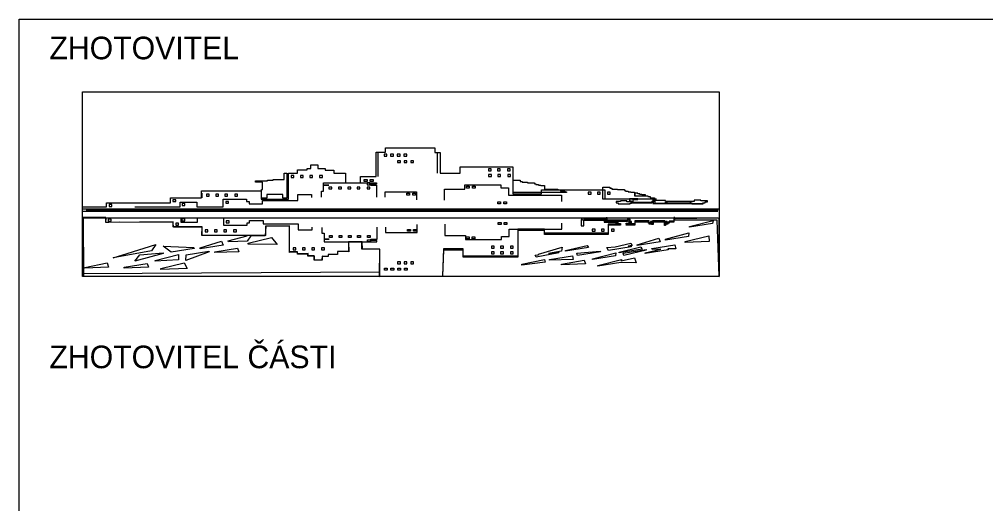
# Model space of a CAD drawing. Extents: x -740053 to -737517, y -1033516 to -1032476.
# Drawn here: x -739091.38 to -739059.3, y -1032591.95 to -1032575.88 of the extents above; entities that cross this region are included whole.
import ezdxf

# ---------------------------------------------------------------- set-up
doc = ezdxf.new("R2010")
doc.units = 0
doc.layers.add('promika-rozp', color=7, linetype='Continuous')

# ---------------------------------------------------------------- blocks, each defined once
blk = doc.blocks.new('onegast')
for p, q in [((22.998, 7.759), (22.998, 9.646)), ((27.598, 8.019), (27.598, 9.571)), ((6.825, 5.723), (6.825, 6.082)), ((9.252, 6.105), (9.252, 6.463)), ((9.309, 6.102), (9.309, 6.46)), ((0.046, 5.264), (49.513, 5.263)), ((0.046, 5.075), (49.427, 5.075)), ((0.046, 4.561), (49.435, 4.561)), ((0.278, 5.186), (49.435, 5.186))]:
    blk.add_line(p, q)
for points in [[(0, 14.352), (49.53, 14.352), (49.53, 0), (0, 0)], [(23.451, 9.351), (23.667, 9.351), (23.667, 9.502), (23.451, 9.502)], [(23.957, 9.351), (24.173, 9.351), (24.173, 9.502), (23.957, 9.502)], [(24.48, 9.351), (24.696, 9.351), (24.696, 9.502), (24.48, 9.502)], [(24.994, 9.351), (25.21, 9.351), (25.21, 9.502), (24.994, 9.502)], [(24.501, 8.843), (24.717, 8.843), (24.717, 8.994), (24.501, 8.994)], [(25.007, 8.843), (25.223, 8.843), (25.223, 8.994), (25.007, 8.994)], [(25.53, 8.843), (25.746, 8.843), (25.746, 8.994), (25.53, 8.994)], [(21.914, 7.53), (22.13, 7.53), (22.13, 7.378), (21.914, 7.378)], [(22.377, 7.53), (22.593, 7.53), (22.593, 7.378), (22.377, 7.378)], [(19.161, 6.799), (19.377, 6.799), (19.377, 6.95), (19.161, 6.95)], [(29.857, 7.022), (30.073, 7.022), (30.073, 6.871), (29.857, 6.871)], [(30.32, 7.022), (30.536, 7.022), (30.536, 6.871), (30.32, 6.871)], [(25.216, 6.462), (25.432, 6.462), (25.432, 6.311), (25.216, 6.311)], [(25.679, 6.462), (25.895, 6.462), (25.895, 6.311), (25.679, 6.311)], [(32.298, 5.793), (32.514, 5.793), (32.514, 5.642), (32.298, 5.642)], [(32.761, 5.793), (32.977, 5.793), (32.977, 5.642), (32.761, 5.642)], [(32.333, 4.18), (32.549, 4.18), (32.549, 4.029), (32.333, 4.029)], [(32.796, 4.18), (33.012, 4.18), (33.012, 4.029), (32.796, 4.029)], [(12.874, 2.574), (14.701, 3.028), (15.132, 2.483), (12.879, 2.512)], [(19.195, 3.182), (19.411, 3.182), (19.411, 3.031), (19.195, 3.031)], [(25.286, 3.656), (25.502, 3.656), (25.502, 3.505), (25.286, 3.505)], [(25.749, 3.656), (25.965, 3.656), (25.965, 3.505), (25.749, 3.505)], [(29.843, 3.074), (30.059, 3.074), (30.059, 2.923), (29.843, 2.923)], [(30.306, 3.074), (30.522, 3.074), (30.522, 2.923), (30.306, 2.923)], [(3.464, 1.792), (5.689, 2.483), (5.353, 1.985), (2.388, 1.451)], [(6.257, 2.359), (8.663, 2.239), (8.678, 2.175), (6.892, 1.886)], [(9.139, 2.21), (10.813, 2.729), (10.929, 2.436), (9.143, 2.148)], [(4.449, 1.687), (6.263, 1.842), (6.277, 1.778), (4.06, 1.174)], [(5.644, 1.239), (7.471, 1.693), (7.457, 1.283), (5.649, 1.176)], [(8.049, 1.674), (9.825, 1.965), (9.84, 1.9), (8.039, 1.247)], [(10.285, 1.911), (12.061, 2.202), (12.15, 1.899), (10.289, 1.849)], [(0.161, 0.692), (1.912, 1.059), (2.012, 0.718), (0.165, 0.63)], [(3.24, 0.71), (5.016, 1), (5.119, 0.715), (3.244, 0.648)], [(6.077, 0.602), (7.903, 1.057), (8.126, 0.622), (6.081, 0.54)], [(24.501, 0.974), (24.717, 0.974), (24.717, 1.125), (24.501, 1.125)], [(25.007, 0.974), (25.223, 0.974), (25.223, 1.125), (25.007, 1.125)], [(25.53, 0.974), (25.746, 0.974), (25.746, 1.125), (25.53, 1.125)], [(23.485, 0.631), (23.701, 0.631), (23.701, 0.48), (23.485, 0.48)], [(23.99, 0.631), (24.206, 0.631), (24.206, 0.48), (23.99, 0.48)], [(24.513, 0.631), (24.729, 0.631), (24.729, 0.48), (24.513, 0.48)], [(25.028, 0.631), (25.244, 0.631), (25.244, 0.48), (25.028, 0.48)]]:
    blk.add_lwpolyline(points, close=True)
for points in [[(0.046, 5.405), (1.862, 5.405), (1.862, 5.731), (6.84, 5.731), (6.84, 6.109), (9.238, 6.109), (9.238, 6.643), (13.878, 6.643), (13.878, 6.005), (16.015, 6.005), (16.015, 8.023), (16.706, 8.023), (16.706, 8.284), (17.475, 8.284), (17.475, 8.401), (17.749, 8.401), (17.749, 8.662), (18.296, 8.662), (18.296, 8.388), (18.879, 8.388), (18.879, 8.272), (19.556, 8.272), (19.556, 8.037), (20.443, 8.037), (20.443, 7.282), (21.616, 7.282), (21.616, 7.764), (22.841, 7.764), (22.841, 9.665), (23.57, 9.665), (23.57, 9.994), (27.389, 9.994), (27.389, 9.629), (27.806, 9.629), (27.806, 8.014), (29.37, 8.014), (29.37, 8.522), (33.462, 8.522), (33.462, 6.412), (35.707, 6.412), (35.707, 6.737), (40.62, 6.737), (40.62, 6.034), (44.351, 6.034), (44.351, 5.656), (48.313, 5.656)], [(31.563, 8.207), (31.779, 8.207), (31.779, 8.358), (31.563, 8.358), (31.563, 8.207)], [(32.276, 8.207), (32.493, 8.207), (32.493, 8.358), (32.276, 8.358), (32.276, 8.207)], [(33.049, 8.207), (33.265, 8.207), (33.265, 8.358), (33.049, 8.358), (33.049, 8.207)], [(14.328, 6.074), (13.905, 6.074), (13.905, 6.765), (14, 6.765), (14, 7.326), (13.453, 7.326), (13.453, 7.425), (14.378, 7.425), (14.378, 7.475), (14.825, 7.475), (14.825, 7.544), (15.233, 7.544), (15.273, 7.544), (15.68, 7.544), (15.68, 8.021), (15.879, 8.021), (15.879, 6.074), (15.571, 6.074), (15.571, 6.362), (14.328, 6.362), (14.328, 6.074)], [(16.228, 7.685), (16.444, 7.685), (16.444, 7.836), (16.228, 7.836), (16.228, 7.685)], [(16.952, 7.685), (17.168, 7.685), (17.168, 7.836), (16.952, 7.836), (16.952, 7.685)], [(17.666, 7.685), (17.882, 7.685), (17.882, 7.836), (17.666, 7.836), (17.666, 7.685)], [(18.439, 7.685), (18.655, 7.685), (18.655, 7.836), (18.439, 7.836), (18.439, 7.685)], [(31.581, 7.761), (31.797, 7.761), (31.797, 7.913), (31.581, 7.913), (31.581, 7.761)], [(32.295, 7.761), (32.511, 7.761), (32.511, 7.913), (32.295, 7.913), (32.295, 7.761)], [(33.067, 7.761), (33.284, 7.761), (33.284, 7.913), (33.067, 7.913), (33.067, 7.761)], [(18.576, 6.169), (18.576, 6.617), (18.746, 6.617), (18.746, 7.081), (19.149, 7.081), (19.149, 7.081), (18.746, 7.081), (18.746, 7.282), (22.862, 7.282), (22.862, 7.282), (22.862, 7.183), (22.396, 7.183), (22.396, 7.088), (22.871, 7.088), (22.871, 6.157)], [(19.919, 6.799), (20.135, 6.799), (20.135, 6.95), (19.919, 6.95), (19.919, 6.799)], [(20.644, 6.799), (20.86, 6.799), (20.86, 6.95), (20.644, 6.95), (20.644, 6.799)], [(21.358, 6.799), (21.574, 6.799), (21.574, 6.95), (21.358, 6.95), (21.358, 6.799)], [(22.13, 6.799), (22.346, 6.799), (22.346, 6.95), (22.13, 6.95), (22.13, 6.799)], [(22.141, 7.131), (22.357, 7.131), (22.357, 7.282), (22.141, 7.282), (22.141, 7.131)], [(28.148, 5.929), (28.148, 6.792), (28.724, 6.792), (28.724, 6.792), (29.741, 6.792), (29.741, 7.118), (30.144, 7.118), (30.144, 7.118), (30.97, 7.118), (30.97, 7.118), (32.543, 7.118), (32.543, 6.888), (33.138, 6.888), (33.138, 6.313), (37.246, 6.313), (37.246, 5.833)], [(37.637, 6.532), (33.482, 6.532), (33.482, 7.473), (34.037, 7.473), (34.037, 7.386), (34.193, 7.386), (34.193, 7.317), (34.616, 7.317), (34.616, 7.275), (35.159, 7.275), (35.159, 7.197), (35.257, 7.197), (35.257, 7.144), (35.467, 7.144), (35.467, 7.095), (35.652, 7.095), (35.652, 7.062), (35.94, 7.062), (35.94, 6.779), (36.976, 6.779), (36.976, 6.725), (37.165, 6.725), (37.165, 6.639), (37.502, 6.639), (37.502, 6.565), (37.637, 6.565), (37.637, 6.532)], [(40.466, 6.007), (40.466, 6.948), (41.021, 6.948), (41.021, 6.861), (41.177, 6.861), (41.177, 6.792), (41.6, 6.792), (41.6, 6.75), (42.143, 6.75), (42.143, 6.672), (42.241, 6.672), (42.241, 6.619), (42.451, 6.619), (42.451, 6.57), (42.636, 6.57), (42.636, 6.537), (42.924, 6.537), (42.924, 6.254), (43.96, 6.254), (43.96, 6.2), (44.149, 6.2), (44.149, 6.114), (44.486, 6.114), (44.486, 6.04), (44.622, 6.04), (44.622, 6.007), (40.466, 6.007)], [(44.622, 6.007), (40.466, 6.007), (40.466, 6.948), (41.021, 6.948), (41.021, 6.861), (41.177, 6.861), (41.177, 6.792), (41.6, 6.792), (41.6, 6.75), (42.143, 6.75), (42.143, 6.672), (42.241, 6.672), (42.241, 6.619), (42.451, 6.619), (42.451, 6.57), (42.636, 6.57), (42.636, 6.537), (42.924, 6.537), (42.924, 6.254), (43.96, 6.254), (43.96, 6.2), (44.149, 6.2), (44.149, 6.114), (44.486, 6.114), (44.486, 6.04), (44.622, 6.04), (44.622, 6.007)], [(4.051, 5.42), (7.596, 5.42), (7.596, 5.765), (8.897, 5.765), (8.897, 5.42), (10.933, 5.42), (10.933, 6.01), (12.761, 6.01), (12.761, 5.826), (12.957, 5.826), (12.957, 5.643), (14, 5.643), (14, 5.888), (16.736, 5.888), (16.736, 6.366), (17.815, 6.366), (17.815, 6.145)], [(9.628, 6.243), (9.844, 6.243), (9.844, 6.394), (9.628, 6.394), (9.628, 6.243)], [(10.353, 6.243), (10.569, 6.243), (10.569, 6.394), (10.353, 6.394), (10.353, 6.243)], [(11.067, 6.243), (11.283, 6.243), (11.283, 6.394), (11.067, 6.394), (11.067, 6.243)], [(11.839, 6.243), (12.055, 6.243), (12.055, 6.394), (11.839, 6.394), (11.839, 6.243)], [(23.534, 6.16), (23.534, 6.579), (25.98, 6.579), (25.98, 5.951)], [(39.341, 6.398), (39.557, 6.398), (39.557, 6.549), (39.341, 6.549), (39.341, 6.398)], [(40.055, 6.398), (40.271, 6.398), (40.271, 6.549), (40.055, 6.549), (40.055, 6.398)], [(40.827, 6.398), (41.043, 6.398), (41.043, 6.549), (40.827, 6.549), (40.827, 6.398)], [(41.512, 5.831), (41.512, 5.707), (41.669, 5.707), (41.669, 5.636), (42.598, 5.636), (42.598, 5.694), (42.709, 5.694), (42.709, 5.727), (44.282, 5.727), (44.282, 5.811), (44.431, 5.811), (44.431, 5.844), (44.516, 5.844), (44.516, 5.681), (45.309, 5.681), (45.309, 5.74), (45.433, 5.74), (45.433, 5.779), (45.491, 5.779), (45.491, 5.805), (47.253, 5.805), (47.253, 5.707), (47.396, 5.707), (47.396, 5.649), (48.254, 5.649), (48.254, 5.727), (48.443, 5.727), (48.443, 5.785), (48.599, 5.785), (48.599, 5.87), (48.098, 5.87), (48.098, 5.922), (47.578, 5.922), (47.578, 5.831), (45.335, 5.831), (45.335, 5.902), (44.425, 5.902), (44.425, 5.772), (44.282, 5.772), (44.282, 5.746), (42.702, 5.746), (42.702, 5.811), (42.826, 5.811), (42.826, 5.967), (43.196, 5.967), (43.196, 6.019), (42.546, 6.019), (42.546, 5.863), (42.683, 5.863), (42.683, 5.798), (42.332, 5.798), (42.332, 5.87), (41.838, 5.87), (41.838, 5.824), (41.512, 5.831)], [(44.282, 5.727), (44.282, 5.746), (42.702, 5.746), (42.702, 5.811), (42.826, 5.811), (42.826, 5.967), (43.196, 5.967), (43.196, 6.019), (42.546, 6.019), (42.546, 5.863), (42.683, 5.863), (42.683, 5.798), (42.332, 5.798), (42.332, 5.87), (41.838, 5.87), (41.838, 5.824), (41.512, 5.831), (41.512, 5.707), (41.669, 5.707), (41.669, 5.636), (42.598, 5.636), (42.598, 5.694), (42.709, 5.694), (42.709, 5.727), (44.282, 5.727)], [(42.958, 6.466), (42.958, 6.276), (43.791, 6.276), (43.791, 6.348), (43.516, 6.348), (43.516, 6.365), (43.342, 6.365), (43.342, 6.413), (43.192, 6.413), (43.192, 6.466), (42.958, 6.466)], [(43.192, 6.466), (42.958, 6.466), (42.958, 6.276), (43.791, 6.276), (43.791, 6.348), (43.516, 6.348), (43.516, 6.365), (43.342, 6.365), (43.342, 6.413), (43.192, 6.413), (43.192, 6.466)], [(2.06, 5.439), (2.276, 5.439), (2.276, 5.591), (2.06, 5.591), (2.06, 5.439)], [(7.024, 5.813), (7.24, 5.813), (7.24, 5.964), (7.024, 5.964), (7.024, 5.813)], [(7.749, 5.505), (7.965, 5.505), (7.965, 5.656), (7.749, 5.656), (7.749, 5.505)], [(11.131, 5.681), (11.348, 5.681), (11.348, 5.832), (11.131, 5.832), (11.131, 5.681)], [(44.425, 5.772), (44.425, 5.811), (44.282, 5.811), (44.282, 5.772), (44.425, 5.772)], [(44.425, 5.902), (44.425, 5.811), (44.431, 5.811), (44.431, 5.844), (44.516, 5.844), (44.516, 5.681), (45.309, 5.681), (45.309, 5.74), (45.433, 5.74), (45.433, 5.779), (45.491, 5.779), (45.491, 5.805), (47.253, 5.805), (47.253, 5.707), (47.396, 5.707), (47.396, 5.649), (48.254, 5.649), (48.254, 5.727), (48.443, 5.727), (48.443, 5.785), (48.599, 5.785), (48.599, 5.87), (48.098, 5.87), (48.098, 5.922), (47.578, 5.922), (47.578, 5.831), (45.335, 5.831), (45.335, 5.902), (44.425, 5.902)], [(0.02, 0.014), (23.093, 0.002), (23.125, 2.114), (22.3, 2.114), (21.766, 2.106), (21.766, 2.114), (21.714, 2.114), (21.714, 2.69), (20.694, 2.699), (20.694, 2.513), (20.708, 1.897), (19.841, 1.924), (19.841, 1.714), (19.819, 1.714), (19.819, 1.69), (19.163, 1.69), (19.103, 1.687), (19.103, 1.544), (18.635, 1.544), (18.625, 1.386), (18.625, 1.266), (18.256, 1.266), (18.026, 1.258), (18.017, 1.57), (17.525, 1.57), (17.525, 1.716), (16.716, 1.716), (16.716, 1.896), (16.101, 1.86), (16.101, 1.902), (16.093, 1.902), (16.093, 2.719), (16.083, 3.915), (14.514, 3.915), (14.249, 3.911), (14.237, 3.714), (14.237, 3.187), (14.206, 3.187), (14.203, 3.146), (13.089, 3.156), (12.812, 2.735), (11.338, 2.693), (11.334, 2.755), (12.803, 3.159), (9.776, 3.187), (9.292, 3.187), (9.292, 3.191), (9.287, 3.191), (9.292, 3.593), (9.292, 3.82), (7.066, 3.831), (7.065, 3.849), (7.039, 3.849), (7.039, 4.196), (2.893, 4.204), (2.028, 4.198), (1.802, 4.187), (1.803, 4.196), (1.802, 4.196), (1.81, 4.518), (0.042, 4.506), (0.02, 0.014)], [(0.042, 4.506), (0.03, 0.238), (23.125, 0.347), (23.125, 2.125), (21.766, 2.106), (21.748, 2.69), (20.689, 2.699), (20.708, 1.897), (19.841, 1.924), (19.841, 1.714), (19.093, 1.687), (19.093, 1.559), (18.637, 1.568), (18.619, 1.277), (18.026, 1.258), (18.017, 1.605), (17.542, 1.596), (17.542, 1.769), (16.721, 1.751), (16.73, 1.897), (16.101, 1.86), (16.083, 3.939), (14.249, 3.911), (14.203, 3.146), (9.287, 3.191), (9.296, 3.82), (7.066, 3.831), (7.048, 4.196), (2.185, 4.205), (1.802, 4.187), (1.821, 4.518), (0.042, 4.506)], [(0.036, 4.579), (0.065, 0.028), (23.119, 0.038), (23.133, 2.114), (21.714, 2.114), (21.714, 2.699), (20.694, 2.699), (20.694, 1.928), (19.819, 1.928), (19.819, 1.69), (19.103, 1.69), (19.103, 1.544), (18.625, 1.544), (18.625, 1.266), (18.029, 1.266), (18.029, 1.57), (17.525, 1.57), (17.525, 1.716), (16.716, 1.716), (16.716, 1.902), (16.093, 1.902), (16.093, 3.915), (14.237, 3.915), (14.237, 3.187), (9.292, 3.187), (9.292, 3.849), (7.039, 3.849), (7.039, 4.233), (1.802, 4.196), (1.811, 4.57), (0.036, 4.579)], [(4.084, 4.561), (7.63, 4.561), (7.63, 4.216), (8.93, 4.216), (8.93, 4.561), (10.967, 4.561), (10.967, 3.971), (12.794, 3.971), (12.794, 4.155), (12.991, 4.155), (12.991, 4.339), (14.034, 4.339), (14.034, 4.094), (16.769, 4.094), (16.769, 3.616), (17.849, 3.616), (17.849, 3.836)], [(28.067, 2.141), (27.991, 0.053), (49.525, -0.002), (49.509, 4.521), (46.076, 4.473), (46.076, 4.57), (46.005, 4.57), (46.005, 4.306), (45.632, 4.306), (45.632, 4.229), (45.529, 4.229), (45.529, 4.146), (45.439, 4.146), (45.349, 4.146), (45.349, 4.036), (45.259, 4.036), (45.259, 4.191), (45.439, 4.146), (45.439, 4.22), (45.439, 4.224), (45.471, 4.224), (45.471, 4.269), (45.282, 4.269), (45.282, 4.316), (44.334, 4.316), (44.334, 4.273), (44.184, 4.273), (44.184, 4.213), (44.287, 4.213), (44.287, 4.176), (44.394, 4.176), (44.394, 4.118), (44.258, 4.118), (44.258, 4.164), (44.068, 4.164), (44.068, 4.218), (44.012, 4.218), (44.012, 4.265), (44.086, 4.265), (44.086, 4.318), (42.971, 4.318), (42.971, 4.076), (42.289, 4.076), (42.289, 4.126), (42.5, 4.126), (42.5, 4.175), (42.652, 4.175), (42.652, 4.222), (42.701, 4.222), (42.701, 4.269), (42.514, 4.269), (42.514, 4.327), (42.596, 4.327), (42.596, 4.458), (42.482, 4.458), (42.482, 4.525), (42.389, 4.525), (42.389, 4.36), (40.819, 4.36), (40.819, 4.547), (40.717, 4.547), (40.717, 4.494), (40.569, 4.494), (40.569, 4.52), (38.993, 4.52), (38.993, 4.465), (40.564, 4.465), (40.564, 4.316), (41.633, 4.316), (41.633, 4.278), (41.484, 4.278), (41.484, 4.169), (41.635, 4.169), (41.635, 4.12), (41.831, 4.12), (41.831, 4.071), (40.874, 4.071), (40.874, 3.353), (35.926, 3.353), (35.926, 3.66), (33.862, 3.66), (33.862, 1.575), (29.594, 1.575), (29.594, 2.142), (28.067, 2.141)], [(1.994, 4.298), (2.21, 4.298), (2.21, 4.449), (1.994, 4.449), (1.994, 4.298)], [(7.243, 3.99), (7.46, 3.99), (7.46, 4.142), (7.243, 4.142), (7.243, 3.99)], [(7.727, 4.32), (7.943, 4.32), (7.943, 4.471), (7.727, 4.471), (7.727, 4.32)], [(11.175, 4.166), (11.391, 4.166), (11.391, 4.317), (11.175, 4.317), (11.175, 4.166)], [(18.61, 3.813), (18.61, 3.364), (18.78, 3.364), (18.78, 2.9), (19.182, 2.9), (19.182, 2.9), (18.78, 2.9), (18.78, 2.699), (22.895, 2.699), (22.895, 2.699), (22.895, 2.799), (22.429, 2.799), (22.429, 2.894), (22.904, 2.894), (22.904, 3.824)], [(23.568, 3.821), (23.568, 3.403), (26.014, 3.403), (26.014, 4.03)], [(28.067, 2.05), (27.99, 0.054), (49.512, 0.016), (49.361, 4.382), (46.076, 4.382), (46.076, 4.478), (46.005, 4.478), (46.005, 4.215), (45.632, 4.215), (45.632, 4.138), (45.529, 4.138), (45.529, 4.054), (45.349, 4.054), (45.349, 3.945), (45.259, 3.945), (45.259, 4.099), (45.439, 4.054), (45.439, 4.129), (45.439, 4.133), (45.471, 4.133), (45.471, 4.178), (45.282, 4.178), (45.282, 4.224), (44.334, 4.224), (44.334, 4.182), (44.184, 4.182), (44.184, 4.122), (44.287, 4.122), (44.287, 4.084), (44.394, 4.084), (44.394, 4.026), (44.258, 4.026), (44.258, 4.073), (44.068, 4.073), (44.068, 4.127), (44.012, 4.127), (44.012, 4.173), (44.086, 4.173), (44.086, 4.227), (42.971, 4.227), (42.971, 3.984), (42.289, 3.984), (42.289, 4.035), (42.5, 4.035), (42.5, 4.084), (42.652, 4.084), (42.652, 4.131), (42.701, 4.131), (42.701, 4.178), (42.514, 4.178), (42.514, 4.235), (42.596, 4.235), (42.596, 4.367), (42.482, 4.367), (42.482, 4.433), (42.389, 4.433), (42.389, 4.269), (40.819, 4.269), (40.819, 4.456), (40.717, 4.456), (40.717, 4.402), (40.569, 4.402), (40.569, 4.429), (38.993, 4.429), (38.993, 4.376), (38.881, 4.376), (38.881, 4.427), (38.792, 4.427), (38.792, 3.942), (38.993, 3.942), (38.993, 4.374), (40.564, 4.374), (40.564, 4.225), (41.633, 4.225), (41.633, 4.187), (41.484, 4.187), (41.484, 4.078), (41.635, 4.078), (41.635, 4.029), (41.831, 4.029), (41.831, 3.98), (40.874, 3.98), (40.874, 3.262), (35.926, 3.262), (35.926, 3.569), (33.862, 3.569), (33.862, 1.483), (29.594, 1.483), (29.594, 2.051), (28.067, 2.05)], [(28.182, 4.052), (28.182, 3.189), (28.757, 3.189), (28.757, 3.189), (29.775, 3.189), (29.775, 2.863), (30.178, 2.863), (30.178, 2.863), (31.003, 2.863), (31.003, 2.863), (32.577, 2.863), (32.577, 3.093), (33.172, 3.093), (33.172, 3.669), (37.279, 3.669), (37.279, 4.148)], [(49.007, 4.105), (47.221, 3.817), (47.216, 3.879), (49.043, 4.334), (49.007, 4.105)], [(9.536, 3.464), (9.752, 3.464), (9.752, 3.615), (9.536, 3.615), (9.536, 3.464)], [(10.26, 3.464), (10.476, 3.464), (10.476, 3.615), (10.26, 3.615), (10.26, 3.464)], [(10.974, 3.464), (11.19, 3.464), (11.19, 3.615), (10.974, 3.615), (10.974, 3.464)], [(11.746, 3.464), (11.963, 3.464), (11.963, 3.615), (11.746, 3.615), (11.746, 3.464)], [(15.132, 2.483), (12.879, 2.512), (12.874, 2.574), (14.701, 3.028), (15.132, 2.483)], [(19.195, 3.031), (19.195, 3.182), (19.411, 3.182), (19.411, 3.031), (19.195, 3.031)], [(20.169, 3.031), (19.953, 3.031), (19.953, 3.182), (20.169, 3.182), (20.169, 3.031)], [(20.893, 3.031), (20.677, 3.031), (20.677, 3.182), (20.893, 3.182), (20.893, 3.031)], [(21.607, 3.031), (21.391, 3.031), (21.391, 3.182), (21.607, 3.182), (21.607, 3.031)], [(22.38, 3.031), (22.164, 3.031), (22.164, 3.182), (22.38, 3.182), (22.38, 3.031)], [(39.65, 3.525), (39.866, 3.525), (39.866, 3.677), (39.65, 3.677), (39.65, 3.525)], [(40.364, 3.525), (40.58, 3.525), (40.58, 3.677), (40.364, 3.677), (40.364, 3.525)], [(41.136, 3.525), (41.352, 3.525), (41.352, 3.677), (41.136, 3.677), (41.136, 3.525)], [(47.132, 3.109), (45.346, 2.82), (45.342, 2.882), (47.162, 3.382), (47.132, 3.109)], [(48.753, 2.715), (46.887, 2.639), (46.882, 2.701), (48.709, 3.155), (48.753, 2.715)], [(2.388, 1.451), (3.464, 1.792), (5.689, 2.483), (5.353, 1.985), (2.388, 1.451)], [(6.892, 1.886), (6.257, 2.359), (8.663, 2.239), (8.678, 2.175), (6.892, 1.886)], [(9.143, 2.148), (9.139, 2.21), (10.813, 2.729), (10.929, 2.436), (9.143, 2.148)], [(22.39, 2.699), (22.174, 2.699), (22.174, 2.85), (22.39, 2.85), (22.39, 2.699)], [(31.804, 2.197), (32.02, 2.197), (32.02, 2.348), (31.804, 2.348), (31.804, 2.197)], [(32.518, 2.197), (32.734, 2.197), (32.734, 2.348), (32.518, 2.348), (32.518, 2.197)], [(33.29, 2.197), (33.506, 2.197), (33.506, 2.348), (33.29, 2.348), (33.29, 2.197)], [(37.045, 1.826), (35.275, 1.483), (35.212, 1.656), (35.458, 1.687), (35.456, 1.725), (37.304, 2.273), (37.246, 1.951), (36.232, 1.787), (37.03, 1.89), (37.045, 1.826)], [(39.361, 2.237), (37.575, 1.949), (37.57, 2.011), (39.263, 2.411), (39.361, 2.237)], [(42.686, 2.302), (40.9, 2.014), (40.791, 2.246), (41.431, 2.287), (42.647, 2.574), (42.745, 2.401), (42.436, 2.351), (42.671, 2.366), (42.686, 2.302)], [(43.522, 2.115), (41.736, 1.826), (41.732, 1.888), (43.425, 2.288), (43.522, 2.115)], [(44.937, 2.689), (43.151, 2.401), (43.147, 2.463), (44.821, 2.982), (44.937, 2.689)], [(45.555, 2.06), (43.769, 1.772), (43.765, 1.834), (44.98, 2.121), (44.297, 2.102), (44.293, 2.164), (46.069, 2.455), (46.158, 2.152), (45.513, 2.135), (45.555, 2.06)], [(4.06, 1.174), (4.449, 1.687), (6.263, 1.842), (6.277, 1.778), (4.06, 1.174)], [(5.649, 1.176), (5.644, 1.239), (7.471, 1.693), (7.457, 1.283), (5.649, 1.176)], [(8.039, 1.247), (8.049, 1.674), (9.825, 1.965), (9.84, 1.9), (8.039, 1.247)], [(10.289, 1.849), (10.285, 1.911), (12.061, 2.202), (12.15, 1.899), (10.289, 1.849)], [(16.383, 2.065), (16.599, 2.065), (16.599, 2.216), (16.383, 2.216), (16.383, 2.065)], [(17.107, 2.065), (17.324, 2.065), (17.324, 2.216), (17.107, 2.216), (17.107, 2.065)], [(17.821, 2.065), (18.037, 2.065), (18.037, 2.216), (17.821, 2.216), (17.821, 2.065)], [(18.594, 2.065), (18.81, 2.065), (18.81, 2.216), (18.594, 2.216), (18.594, 2.065)], [(31.804, 1.752), (32.02, 1.752), (32.02, 1.903), (31.804, 1.903), (31.804, 1.752)], [(32.518, 1.752), (32.734, 1.752), (32.734, 1.903), (32.518, 1.903), (32.518, 1.752)], [(33.29, 1.752), (33.506, 1.752), (33.506, 1.903), (33.29, 1.903), (33.29, 1.752)], [(38.172, 1.324), (36.328, 1.254), (36.324, 1.316), (38.1, 1.607), (38.172, 1.324)], [(40.285, 1.905), (38.499, 1.617), (38.457, 1.814), (40.271, 1.97), (40.285, 1.905)], [(41.443, 1.592), (39.657, 1.304), (39.653, 1.366), (41.479, 1.82), (41.443, 1.592)], [(43.848, 2.028), (42.108, 1.637), (42.057, 1.801), (43.833, 2.092), (43.848, 2.028)], [(0.165, 0.63), (0.161, 0.692), (1.912, 1.059), (2.012, 0.718), (0.165, 0.63)], [(3.244, 0.648), (3.24, 0.71), (5.016, 1), (5.119, 0.715), (3.244, 0.648)], [(6.081, 0.54), (6.077, 0.602), (7.903, 1.057), (8.126, 0.622), (6.081, 0.54)], [(35.996, 1.11), (34.173, 0.883), (34.169, 0.945), (35.92, 1.312), (35.996, 1.11)], [(39.127, 0.968), (37.252, 0.901), (37.248, 0.963), (39.024, 1.253), (39.127, 0.968)], [(41.875, 1.082), (40.089, 0.793), (40.085, 0.855), (41.911, 1.31), (41.894, 1.2), (42.92, 1.442), (43.064, 1.042), (41.875, 1.085), (41.875, 1.082)]]:
    blk.add_lwpolyline(points)

msp = doc.modelspace()

# ---------------------------------------------------------------- linework, layer by layer
at = {"layer": 'promika-rozp'}
msp.add_lwpolyline([(-739091.385, -1032596.382), (-739091.385, -1032575.882), (-739001.385, -1032575.882), (-739001.385, -1032596.382)], dxfattribs=at)

# ---------------------------------------------------------------- block references
at = {"xscale": 0.4267458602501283, "yscale": 0.4267458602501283}
msp.add_blockref('onegast', (-739089.284, -1032584.411), dxfattribs=at)

# ---------------------------------------------------------------- texts
at = {"layer": 'promika-rozp'}
for s, p in [('ZHOTOVITEL', (-739090.386, -1032577.207)), ('ZHOTOVITEL ČÁSTI', (-739090.386, -1032587.457))]:
    msp.add_text(s, height=0.75, dxfattribs=at).set_placement(p)

doc.saveas('drawing.dxf')
